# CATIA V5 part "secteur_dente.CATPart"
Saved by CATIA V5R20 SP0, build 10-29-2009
Part number: secteur_dente
Definition: NONE
Nomenclature: 1
Source: Unknown
Description: PART-1-DESC
Bounding box of the stored display mesh (mm): x -2.492 to 7.508, y -32.464 to 7.111, z -10.491 to 10.491
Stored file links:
  F:\Catia_finish\secteur_dente.CATPart
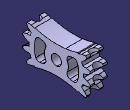
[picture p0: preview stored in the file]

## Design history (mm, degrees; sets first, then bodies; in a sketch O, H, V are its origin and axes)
Sketch1 on zx-plane, origin (0, 0, 0), H (-1, 0, 0), V (0, 0, 1)
  line L1 (-7.5079, -25) -> (-36.5079, -25)
  line L2 (-36.5079, -25) -> (-36.5079, 24)
  line L3 (-36.5079, 24) -> (-7.5079, 24)
  line L4 (-7.5079, 24) -> (-7.5079, -25)
  reference projected point E1 (2.4921, -18.5907) from vertex [face of Solid1 | face of Solid1 | face of Solid1]
  distance L4 E1 = 10
  horizontal: L1 H, L3 H
  vertical: L2 V, L4 V
Solid1: solid without history
Body1 "1" (main body)
  Pocket1: profile Sketch1, direction (0, -1, 0), length 35, opposite side length 30
  Sketch2 on face of Pocket1 from Sketch1.L4, origin (7.5079, 0, 0), H (0, 1, 0), V (0, 0, 1)
    circle A1 centre (-12.6767, 0) radius 6
    point P1 (-12.6767, 0)
    reference projected arc E1 centre (-12.6767, 0) radius 6 from (-12.6767, 6) to (-12.6767, -6) ccw from edge [face of Solid1 | face of Pocket1 from Sketch1.L4]
    radius A1 = 6
    coincidence: P1 H
    concentricity: P1 E1
  Pad1: profile Sketch2, direction (-1, 0, 0), length 10
  Sketch3 on face of Pad1, origin (7.5079, 0, 0), H (0, 1, 0), V (0, 0, 1)
    circle A1 centre (-12.6767, 0) radius 3
    point P1 (-12.6767, 0)
    reference projected arc E1 centre (-12.6767, 0) radius 16 from (0.1573, 9.5545) to (-1.0387, 10.9799) ccw from edge [face of Pad1 | face of Solid1]
    circle A2 centre (-12.6767, 50) radius 42
    point P2 (-12.6767, 50)
    circle A3 centre (-12.6767, -50) radius 42
    point P3 (-12.6767, -50)
    axis line L1 (-12.6767, 0) -> (-12.6767, -45)
    radius A1 = 3
    distance P2 P3 = 100
    distance P3 P1 = 50 {= Sketch3.distance(P2 P3) /2}
    radius A2 = 42
    radius A3 = 42 {= Sketch3.radius(A2)}
    concentricity: P1 E1
    vertical: L1 V
    coincidence: P2 L1, P3 L1
  Pocket2: profile Sketch3, direction (1, 0, 0), through (limit type 3)
  Sketch4 on face of Pad1, origin (7.5079, 0, 0), H (0, 1, 0), V (0, 0, 1)
    arc A1 centre (-12.6767, 0) radius 13 from (-23.9694, 6.44) to (-23.9694, -6.44) ccw
    point P1 (-12.6767, 0)
    arc A2 centre (-12.6767, 0) radius 7 from (-17.3181, 5.24) to (-17.3181, -5.24) ccw
    point P2 (-12.6767, 0)
    reference projected circle E1 centre (-12.6767, 0) radius 3 from edge [face of Pad1 | face of Pocket2 from Sketch3.A1]
    arc A3 centre (-12.6767, 50) radius 45 from (-23.9694, 6.44) to (-17.3181, 5.24) ccw
    arc A4 centre (-12.6767, -50) radius 45 from (-1.3839, -6.44) to (-8.0353, -5.24) ccw
    reference projected arc E2 centre (-12.6767, 50) radius 42 from (-25.2303, 9.92) to (-0.1231, 9.92) ccw from edge [face of Pad1 | face of Pocket2 from Sketch3.A2]
    reference projected arc E3 centre (-12.6767, -50) radius 42 from (-0.1231, -9.92) to (-25.2303, -9.92) ccw from edge [face of Pad1 | face of Pocket2 from Sketch3.A3]
    point P8 (-1.3839, -6.44)
    arc A5 centre (-12.6767, 0) radius 13 from (-1.3839, -6.44) to (-1.3839, 6.44) ccw
    point P9 (-8.0353, 5.24)
    arc A6 centre (-12.6767, 50) radius 45 from (-8.0353, 5.24) to (-1.3839, 6.44) ccw
    point P11 (-8.0353, -5.24)
    arc A7 centre (-12.6767, -50) radius 45 from (-17.3181, -5.24) to (-23.9694, -6.44) ccw
    arc A8 centre (-12.6767, 0) radius 7 from (-8.0353, -5.24) to (-8.0353, 5.24) ccw
    radius A2 = 7
    radius A1 = 13
    radius A4 = 45 {= Sketch4.radius(A3)}
    radius A3 = 45
    coincidence: P2 P1, A1 P8, A1 A5, A3 P9, A3 A6, A2 P11, A4 A7, A2 A8
    concentricity: A2 E1, A3 E2, A4 E3
  Pocket3: profile Sketch4, direction (1, 0, 0), through (limit type 3)
  Fillet1: radius 2, on edge [face of Pocket3 from Sketch4.A8 | face of Pocket3 from Sketch4.A6]; edge [face of Pocket3 from Sketch4.A4 | face of Pocket3 from Sketch4.A8]; edge [face of Pocket3 from Sketch4.A3 | face of Pocket3 from Sketch4.A2]; edge [face of Pocket3 from Sketch4.A2 | face of Pocket3 from Sketch4.A7]
  Fillet2: radius 2, on edge [face of Pocket3 from Sketch4.A1 | face of Pocket3 from Sketch4.A3]; edge [face of Pocket3 from Sketch4.A6 | face of Pocket3 from Sketch4.A5]; edge [face of Pocket3 from Sketch4.A5 | face of Pocket3 from Sketch4.A4]; edge [face of Pocket3 from Sketch4.A7 | face of Pocket3 from Sketch4.A1]
  Sketch5 on xy-plane, origin (0, 0, 0), H (1, 0, 0), V (0, 1, 0)
    circle A1 centre (2.5079, 7.3233) radius 2.5
    point P1 (2.5079, 7.3233)
    reference projected line E1 through (0, -12.6767) direction (1, 0) from axis of face of Pocket2 from Sketch3.A1
    reference projected line E2 (-2.4921, -25.2303) -> (-2.4921, -0.1231) from edge [face of Pocket2 from Sketch3.A2 | face of Pad1]
    distance P1 E1 = 20
    radius A1 = 2.5
    distance P1 E2 = 5
  Groove1: profile Sketch5, axis axis of face of Pocket2 from Sketch3.A1, angle 360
